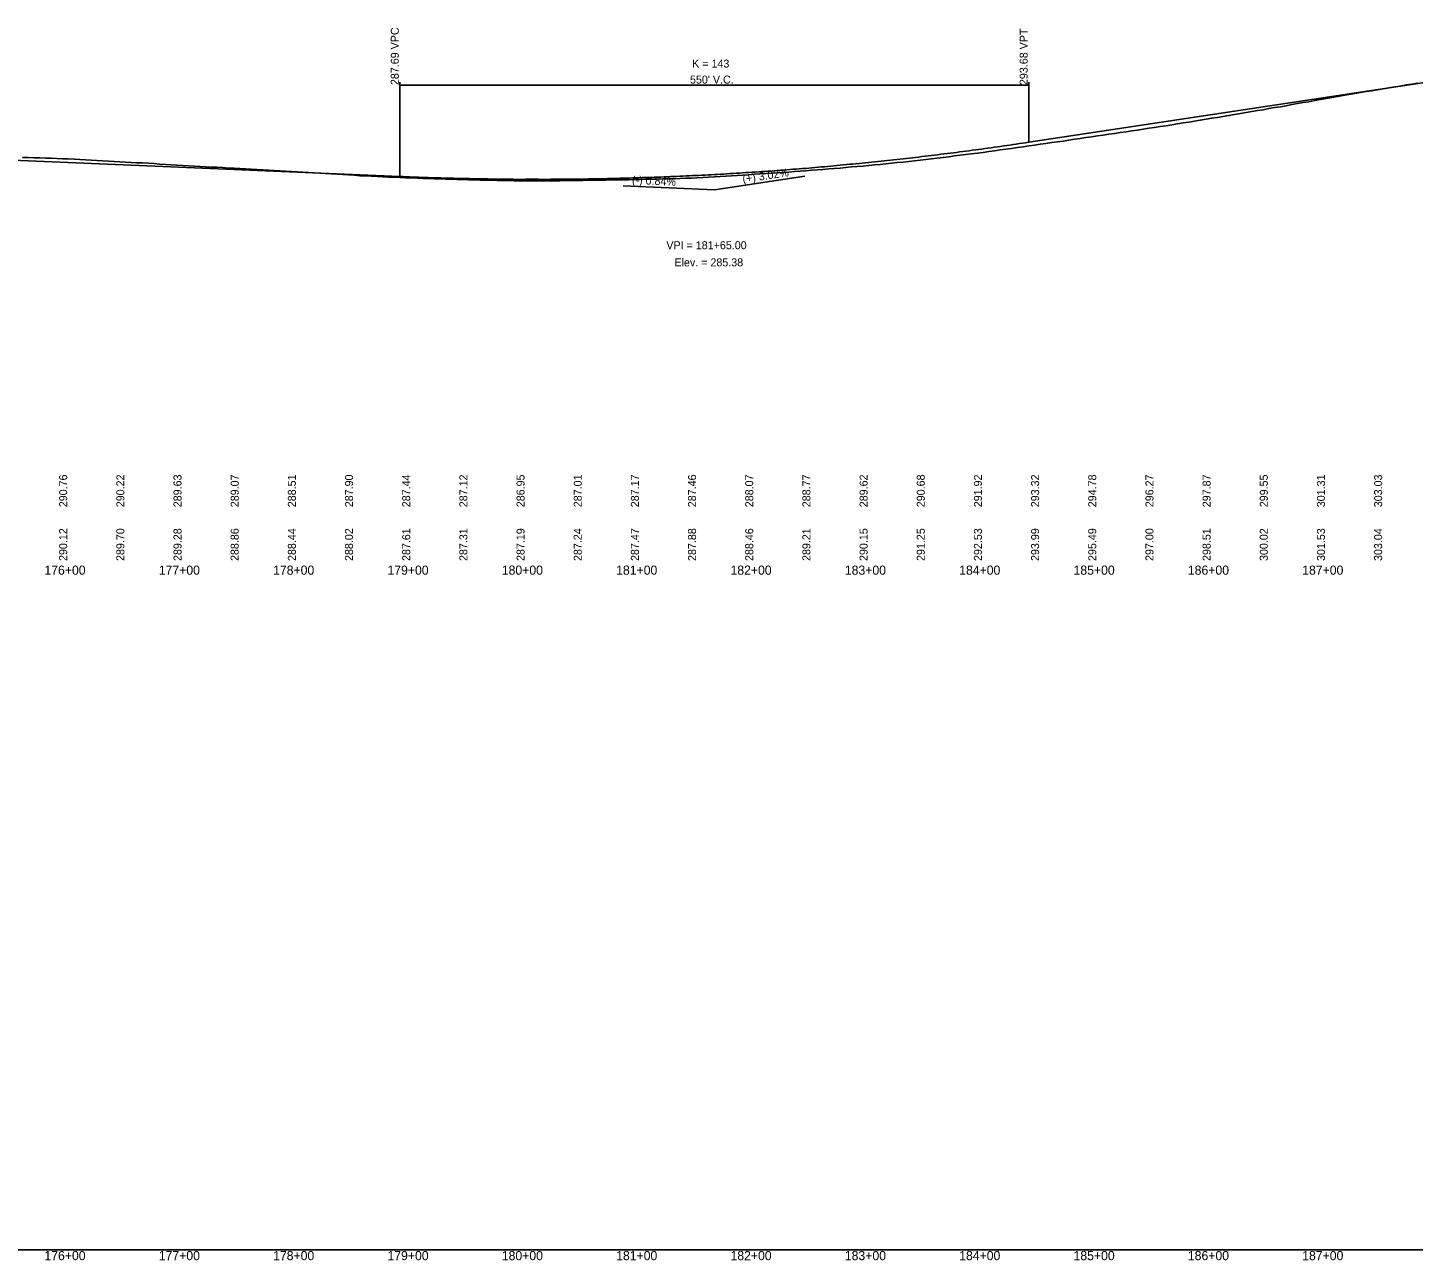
# Model space of a CAD drawing. Extents: x 1838386 to 1955906, y 719739 to 834437.
# Drawn here: x 1894928 to 1896139, y 823083 to 824160 of the extents above; entities that cross this region are included whole.
import ezdxf

# ---------------------------------------------------------------- set-up
doc = ezdxf.new("R2010")
doc.units = 0
for name, color, linetype in [('RD_DDB_GradeTX', 7, 'Continuous'), ('RD_DDB_Profile_EX', 7, 'Continuous'), ('RD_DDB_Profile_Lbl', 7, 'Continuous'), ('RD_DDB_Profile_PR', 7, 'Continuous'), ('RD_DDB_StaTX', 7, 'Continuous'), ('RD_DDB_StripGrade', 7, 'Continuous'), ('RD_DDB_VCLbl', 7, 'Continuous'), ('RD_GPK_Profile_Cell', 7, 'Continuous')]:
    doc.layers.add(name, color=color, linetype=linetype)

msp = doc.modelspace()

# ---------------------------------------------------------------- linework, layer by layer
at = {"layer": 'RD_DDB_GradeTX'}
for p in [(1895448.2, 824021.9), (1895607.2, 824030.5)]:
    msp.add_line(p, (1895528.1, 824018.5), dxfattribs=at)
at = {"layer": 'RD_DDB_Profile_EX'}
for points in [[(1895658.1, 824039.2), (1895663.1, 824039.7), (1895668.1, 824040.2), (1895673.1, 824040.7), (1895678.1, 824041.2), (1895683.1, 824041.7), (1895688.1, 824042.2), (1895693.1, 824042.7), (1895698.1, 824043.3), (1895703.1, 824043.9), (1895708.1, 824044.4), (1895713.1, 824045), (1895718.1, 824045.6), (1895723.1, 824046.2), (1895728.1, 824046.8), (1895733.1, 824047.4), (1895738.1, 824048), (1895743.1, 824048.6), (1895748.1, 824049.2), (1895753.1, 824049.9), (1895758.1, 824050.5), (1895763.1, 824051.2), (1895768.1, 824051.9), (1895773.1, 824052.6), (1895778.1, 824053.3), (1895783.1, 824054), (1895788.1, 824054.7), (1895793.1, 824055.4), (1895798.1, 824056.1), (1895803.1, 824056.8), (1895808.1, 824057.5), (1895813.1, 824058.2), (1895818.1, 824058.9), (1895823.1, 824059.7), (1895828.1, 824060.4), (1895833.1, 824061.1), (1895838.1, 824061.8), (1895843.1, 824062.6), (1895848.1, 824063.3), (1895853.1, 824064.1), (1895858.1, 824064.8), (1895863.1, 824065.5), (1895868.1, 824066.3), (1895873.1, 824067), (1895878.1, 824067.8), (1895883.1, 824068.5), (1895888.1, 824069.2), (1895893.1, 824070), (1895898.1, 824070.7), (1895903.1, 824071.5), (1895908.1, 824072.2), (1895913.1, 824073), (1895918.1, 824073.8), (1895923.1, 824074.5), (1895928.1, 824075.3), (1895933.1, 824076.1), (1895938.1, 824076.9), (1895943.1, 824077.7), (1895948.1, 824078.5), (1895953.1, 824079.3), (1895958.1, 824080.2), (1895963.1, 824081), (1895968.1, 824081.8), (1895973.1, 824082.6), (1895978.1, 824083.4), (1895983.1, 824084.3), (1895988.1, 824085.1), (1895993.1, 824086), (1895998.1, 824086.8), (1896003.1, 824087.7), (1896008.1, 824088.5), (1896013.1, 824089.4), (1896018.1, 824090.3), (1896023.1, 824091.1), (1896028.1, 824092), (1896033.1, 824092.9), (1896038.1, 824093.8), (1896043.1, 824094.7), (1896048.1, 824095.5), (1896053.1, 824096.4), (1896058.1, 824097.3), (1896063.1, 824098.2), (1896068.1, 824099.1), (1896073.1, 824099.9), (1896078.1, 824100.8), (1896083.1, 824101.7), (1896088.1, 824102.6), (1896093.1, 824103.4), (1896098.1, 824104.3), (1896103.1, 824105.1), (1896108.1, 824105.9), (1896113.1, 824106.8), (1896118.1, 824107.6), (1896123.1, 824108.4), (1896128.1, 824109.2), (1896133.1, 824110.1), (1896138.1, 824110.9), (1896143.1, 824111.7)], [(1894923.1, 824046.8), (1894928.1, 824046.7), (1894933.1, 824046.5), (1894938.1, 824046.4), (1894943.1, 824046.2), (1894948.1, 824046), (1894953.1, 824045.8), (1894958.1, 824045.6), (1894963.1, 824045.4), (1894968.1, 824045.2), (1894973.1, 824045), (1894978.1, 824044.7), (1894983.1, 824044.4), (1894988.1, 824044.2), (1894993.1, 824043.9), (1894998.1, 824043.6), (1895003.1, 824043.3), (1895008.1, 824043), (1895013.1, 824042.7), (1895018.1, 824042.4), (1895023.1, 824042.1), (1895028.1, 824041.9), (1895033.1, 824041.6), (1895038.1, 824041.3), (1895043.1, 824041), (1895048.1, 824040.7), (1895053.1, 824040.4), (1895058.1, 824040.1), (1895063.1, 824039.8), (1895068.1, 824039.5), (1895073.1, 824039.2), (1895078.1, 824038.9), (1895083.1, 824038.6), (1895088.1, 824038.3), (1895093.1, 824038.1), (1895098.1, 824037.8), (1895103.1, 824037.5), (1895108.1, 824037.3), (1895113.1, 824037), (1895118.1, 824036.7), (1895123.1, 824036.5), (1895128.1, 824036.2), (1895133.1, 824035.9), (1895138.1, 824035.6), (1895143.1, 824035.3), (1895148.1, 824035), (1895153.1, 824034.7), (1895158.1, 824034.4)], [(1895158.1, 824034.4), (1895163.1, 824034.1), (1895168.1, 824033.8), (1895173.1, 824033.6), (1895178.1, 824033.3), (1895183.1, 824033), (1895188.1, 824032.7), (1895193.1, 824032.4), (1895198.1, 824032), (1895203.1, 824031.8), (1895208.1, 824031.4), (1895213.1, 824031.1), (1895218.1, 824030.8), (1895223.1, 824030.6), (1895228.1, 824030.3), (1895233.1, 824030.1), (1895238.1, 824029.8), (1895243.1, 824029.6), (1895248.1, 824029.4), (1895253.1, 824029.2), (1895258.1, 824029), (1895263.1, 824028.8), (1895268.1, 824028.6), (1895273.1, 824028.4), (1895278.1, 824028.3), (1895283.1, 824028.1), (1895288.1, 824027.9), (1895293.1, 824027.8), (1895298.1, 824027.6), (1895303.1, 824027.5), (1895308.1, 824027.4), (1895313.1, 824027.2), (1895318.1, 824027.1), (1895323.1, 824027), (1895328.1, 824026.9), (1895333.1, 824026.8), (1895338.1, 824026.7), (1895343.1, 824026.6), (1895348.1, 824026.5), (1895353.1, 824026.4), (1895358.1, 824026.4), (1895363.1, 824026.4), (1895368.1, 824026.3), (1895373.1, 824026.3), (1895378.1, 824026.3), (1895383.1, 824026.4), (1895388.1, 824026.4), (1895393.1, 824026.4), (1895398.1, 824026.5), (1895403.1, 824026.5), (1895408.1, 824026.6), (1895413.1, 824026.7), (1895418.1, 824026.8), (1895423.1, 824026.8), (1895428.1, 824026.9), (1895433.1, 824027), (1895438.1, 824027.1), (1895443.1, 824027.1), (1895448.1, 824027.2), (1895453.1, 824027.3), (1895458.1, 824027.4), (1895463.1, 824027.5), (1895468.1, 824027.6), (1895473.1, 824027.7), (1895478.1, 824027.8), (1895483.1, 824027.9), (1895488.1, 824028), (1895493.1, 824028.1), (1895498.1, 824028.3), (1895503.1, 824028.5), (1895508.1, 824028.7), (1895513.1, 824028.9), (1895518.1, 824029.1), (1895523.1, 824029.4), (1895528.1, 824029.7), (1895533.1, 824030), (1895538.1, 824030.3), (1895543.1, 824030.7), (1895548.1, 824031), (1895553.1, 824031.3), (1895558.1, 824031.6), (1895563.1, 824032), (1895568.1, 824032.3), (1895573.1, 824032.6), (1895578.1, 824033), (1895583.1, 824033.3), (1895588.1, 824033.7), (1895593.1, 824034), (1895598.1, 824034.4), (1895603.1, 824034.7), (1895608.1, 824035.1), (1895613.1, 824035.5), (1895618.1, 824035.9), (1895623.1, 824036.3), (1895628.1, 824036.7), (1895633.1, 824037.1), (1895638.1, 824037.5), (1895643.1, 824038), (1895648.1, 824038.4), (1895653.1, 824038.8), (1895658.1, 824039.2)]]:
    msp.add_lwpolyline(points, dxfattribs=at)
at = {"layer": 'RD_DDB_Profile_PR'}
for p, q in [((1895803.1, 824060), (1896450.1, 824157.7)), ((1894893.1, 824045.1), (1895253.1, 824030.1))]:
    msp.add_line(p, q, dxfattribs=at)
msp.add_spline([(1895253.1, 824030.1), (1895264.1, 824029.6), (1895275.1, 824029.2), (1895286.1, 824028.9), (1895297.1, 824028.6), (1895308.1, 824028.3), (1895319.1, 824028.1), (1895330.1, 824027.9), (1895341.1, 824027.7), (1895352.1, 824027.6), (1895363.1, 824027.6), (1895374.1, 824027.6), (1895385.1, 824027.6), (1895396.1, 824027.7), (1895407.1, 824027.8), (1895418.1, 824027.9), (1895429.1, 824028.1), (1895440.1, 824028.4), (1895451.1, 824028.6), (1895462.1, 824029), (1895473.1, 824029.3), (1895484.1, 824029.7), (1895495.1, 824030.2), (1895506.1, 824030.7), (1895517.1, 824031.2), (1895528.1, 824031.8), (1895539.1, 824032.4), (1895550.1, 824033.1), (1895561.1, 824033.8), (1895572.1, 824034.5), (1895583.1, 824035.3), (1895594.1, 824036.2), (1895605.1, 824037), (1895616.1, 824037.9), (1895627.1, 824038.9), (1895638.1, 824039.9), (1895649.1, 824041), (1895660.1, 824042), (1895671.1, 824043.2), (1895682.1, 824044.3), (1895693.1, 824045.6), (1895704.1, 824046.8), (1895715.1, 824048.1), (1895726.1, 824049.5), (1895737.1, 824050.8), (1895748.1, 824052.3), (1895759.1, 824053.7), (1895770.1, 824055.2), (1895781.1, 824056.8), (1895792.1, 824058.4), (1895803.1, 824060)], degree=3, dxfattribs=at)
at = {"layer": 'RD_DDB_VCLbl'}
for p, q in [((1895253.1, 824112.5), (1895253.1, 824030.1)), ((1895253.1, 824110), (1895803.1, 824110)), ((1895803.1, 824112.5), (1895803.1, 824060))]:
    msp.add_line(p, q, dxfattribs=at)
at = {"layer": 'RD_GPK_Profile_Cell'}
msp.add_line((1878363.1, 823091.6), (1904963.1, 823091.6), dxfattribs=at)

# ---------------------------------------------------------------- texts
at = {"layer": 'RD_DDB_GradeTX'}
for s, rotation, p in [('(+) 3.02%', 8.5809, (1895553.2, 824024.3)), ('(-) 0.84%', 357.6017, (1895455.9, 824023.6))]:
    msp.add_text(s, height=7, rotation=rotation, dxfattribs=at).set_placement(p)
at = {"layer": 'RD_DDB_Profile_Lbl'}
for s, p in [('VPI = 181+65.00', (1895486.1, 823966.5)), ('Elev. = 285.38', (1895493.2, 823951.5))]:
    msp.add_text(s, height=7, dxfattribs=at).set_placement(p)
at = {"layer": 'RD_DDB_StaTX'}
for s, p in [('176+00', (1894942.2, 823681.9)), ('177+00', (1895042.2, 823681.9)), ('178+00', (1895142.2, 823681.9)), ('179+00', (1895242.2, 823681.9)), ('180+00', (1895342.2, 823681.9)), ('181+00', (1895442.2, 823681.9)), ('182+00', (1895542.2, 823681.9)), ('183+00', (1895642.2, 823681.9)), ('184+00', (1895742.2, 823681.9)), ('185+00', (1895842.2, 823681.9)), ('186+00', (1895942.2, 823681.9)), ('187+00', (1896042.2, 823681.9)), ('176+00', (1894942.2, 823082.6)), ('177+00', (1895042.2, 823082.6)), ('178+00', (1895142.2, 823082.6)), ('179+00', (1895242.2, 823082.6)), ('180+00', (1895342.2, 823082.6)), ('181+00', (1895442.2, 823082.6)), ('182+00', (1895542.2, 823082.6)), ('183+00', (1895642.2, 823082.6)), ('184+00', (1895742.2, 823082.6)), ('185+00', (1895842.2, 823082.6)), ('186+00', (1895942.2, 823082.6)), ('187+00', (1896042.2, 823082.6))]:
    msp.add_text(s, height=8, dxfattribs=at).set_placement(p)
at = {"layer": 'RD_DDB_StripGrade'}
for s, p in [('287.69 VPC', (1895252.1, 824110)), ('293.68 VPT', (1895802.1, 824110)), ('290.76', (1894962.1, 823740.9)), ('290.22', (1895012.1, 823740.9)), ('289.63', (1895062.1, 823740.9)), ('289.07', (1895112.1, 823740.9)), ('288.51', (1895162.1, 823740.9)), ('287.90', (1895212.1, 823740.9)), ('287.44', (1895262.1, 823740.9)), ('287.12', (1895312.1, 823740.9)), ('286.95', (1895362.1, 823740.9)), ('287.01', (1895412.1, 823740.9)), ('287.17', (1895462.1, 823740.9)), ('287.46', (1895512.1, 823740.9)), ('288.07', (1895562.1, 823740.9)), ('288.77', (1895612.1, 823740.9)), ('289.62', (1895662.1, 823740.9)), ('290.68', (1895712.1, 823740.9)), ('291.92', (1895762.1, 823740.9)), ('293.32', (1895812.1, 823740.9)), ('294.78', (1895862.1, 823740.9)), ('296.27', (1895912.1, 823740.9)), ('297.87', (1895962.1, 823740.9)), ('299.55', (1896012.1, 823740.9)), ('301.31', (1896062.1, 823740.9)), ('303.03', (1896112.1, 823740.9)), ('290.12', (1894962.1, 823693.9)), ('289.70', (1895012.1, 823693.9)), ('289.28', (1895062.1, 823693.9)), ('288.86', (1895112.1, 823693.9)), ('288.44', (1895162.1, 823693.9)), ('288.02', (1895212.1, 823693.9)), ('287.61', (1895262.1, 823693.9)), ('287.31', (1895312.1, 823693.9)), ('287.19', (1895362.1, 823693.9)), ('287.24', (1895412.1, 823693.9)), ('287.47', (1895462.1, 823693.9)), ('287.88', (1895512.1, 823693.9)), ('288.46', (1895562.1, 823693.9)), ('289.21', (1895612.1, 823693.9)), ('290.15', (1895662.1, 823693.9)), ('291.25', (1895712.1, 823693.9)), ('292.53', (1895762.1, 823693.9)), ('293.99', (1895812.1, 823693.9)), ('295.49', (1895862.1, 823693.9)), ('297.00', (1895912.1, 823693.9)), ('298.51', (1895962.1, 823693.9)), ('300.02', (1896012.1, 823693.9)), ('301.53', (1896062.1, 823693.9)), ('303.04', (1896112.1, 823693.9))]:
    msp.add_text(s, height=7, rotation=90, dxfattribs=at).set_placement(p)
at = {"layer": 'RD_DDB_VCLbl'}
for s, p in [('K = 143', (1895508.7, 824125.3)), ("550' V.C.", (1895506.8, 824111.3))]:
    msp.add_text(s, height=7, dxfattribs=at).set_placement(p)

doc.saveas('drawing.dxf')
